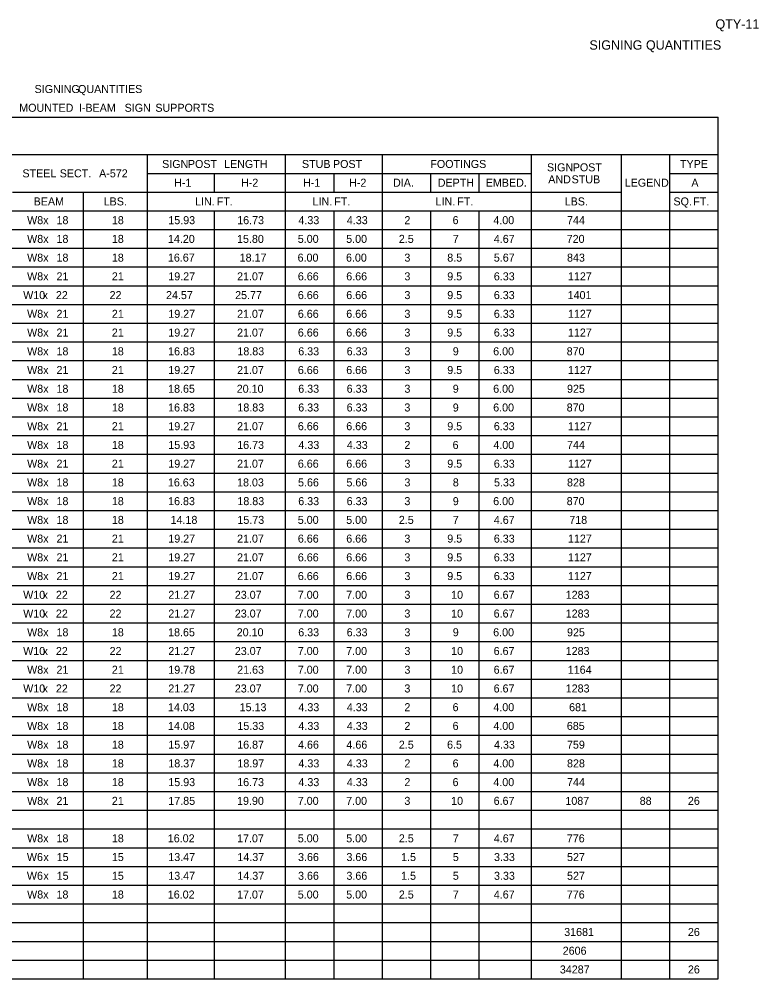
# Model space of a CAD drawing. Extents: x 1226631 to 1228126, y 151309 to 152305.
# Drawn here: x 1227650 to 1228112, y 151706 to 152305 of the extents above; entities that cross this region are included whole.
import ezdxf

# ---------------------------------------------------------------- set-up
doc = ezdxf.new("R2010")
doc.units = 0
doc.layers.add('R_Border', color=7, linetype='Continuous')
doc.layers.add('R_Dimension', color=7, linetype='Continuous')

msp = doc.modelspace()

# ---------------------------------------------------------------- linework, layer by layer
at = {"layer": 'R_Dimension'}
for p, q in [((1227303.08, 152244.32), (1228086.49, 152244.32)), ((1228086.49, 151706.12), (1228086.49, 152244.32)), ((1227540.49, 152220.92), (1228086.49, 152220.92)), ((1227730.13, 151706.12), (1227730.13, 152220.92)), ((1227816.42, 151706.12), (1227816.42, 152220.92)), ((1227876.87, 151706.12), (1227876.87, 152220.92)), ((1227969.98, 151706.12), (1227969.98, 152220.92)), ((1228026.04, 151706.12), (1228026.04, 152220.92)), ((1228056.27, 151706.12), (1228056.27, 152220.92)), ((1227730.13, 152209.22), (1227969.98, 152209.22)), ((1227772.05, 152197.52), (1227772.05, 152209.22)), ((1227846.64, 152197.52), (1227846.64, 152209.22)), ((1227907.09, 152197.52), (1227907.09, 152209.22)), ((1227937.32, 152197.52), (1227937.32, 152209.22)), ((1228056.27, 152209.22), (1228086.49, 152209.22)), ((1227645.79, 152197.52), (1228026.04, 152197.52)), ((1227690.15, 151706.12), (1227690.15, 152197.52)), ((1227969.98, 152197.52), (1228026.04, 152197.52)), ((1228056.27, 152197.52), (1228086.49, 152197.52)), ((1227303.08, 152185.82), (1228086.49, 152185.82)), ((1227772.05, 151706.12), (1227772.05, 152185.82)), ((1227846.64, 151706.12), (1227846.64, 152185.82)), ((1227907.09, 151706.12), (1227907.09, 152185.82)), ((1227937.32, 151706.12), (1227937.32, 152185.82)), ((1228026.04, 152185.82), (1228086.49, 152185.82)), ((1227303.08, 152174.12), (1228086.49, 152174.12)), ((1227303.08, 152162.42), (1228086.49, 152162.42)), ((1227303.08, 152150.72), (1228086.49, 152150.72)), ((1227303.08, 152139.02), (1228086.49, 152139.02)), ((1227303.08, 152127.32), (1228086.49, 152127.32)), ((1227303.08, 152115.62), (1228086.49, 152115.62)), ((1227303.08, 152103.92), (1228086.49, 152103.92)), ((1227303.08, 152092.22), (1228086.49, 152092.22)), ((1227303.08, 152080.52), (1228086.49, 152080.52)), ((1227303.08, 152068.82), (1228086.49, 152068.82)), ((1227303.08, 152057.12), (1228086.49, 152057.12)), ((1227303.08, 152045.42), (1228086.49, 152045.42)), ((1227303.08, 152033.72), (1228086.49, 152033.72)), ((1227303.08, 152022.02), (1228086.49, 152022.02)), ((1227303.08, 152010.32), (1228086.49, 152010.32)), ((1227303.08, 151998.62), (1228086.49, 151998.62)), ((1227303.08, 151986.92), (1228086.49, 151986.92)), ((1227303.08, 151975.22), (1228086.49, 151975.22)), ((1227303.08, 151963.52), (1228086.49, 151963.52)), ((1227303.08, 151951.82), (1228086.49, 151951.82)), ((1227303.08, 151940.12), (1228086.49, 151940.12)), ((1227303.08, 151928.42), (1228086.49, 151928.42)), ((1227303.08, 151916.72), (1228086.49, 151916.72)), ((1227303.08, 151905.02), (1228086.49, 151905.02)), ((1227303.08, 151893.32), (1228086.49, 151893.32)), ((1227303.08, 151881.62), (1228086.49, 151881.62)), ((1227303.08, 151869.92), (1228086.49, 151869.92)), ((1227303.08, 151858.22), (1228086.49, 151858.22)), ((1227303.08, 151846.52), (1228086.49, 151846.52)), ((1227303.08, 151834.82), (1228086.49, 151834.82)), ((1227303.08, 151823.12), (1228086.49, 151823.12)), ((1227303.08, 151811.42), (1228086.49, 151811.42)), ((1227303.08, 151799.72), (1228086.49, 151799.72)), ((1227303.08, 151788.02), (1228086.49, 151788.02)), ((1227303.08, 151776.32), (1228086.49, 151776.32)), ((1227303.08, 151764.62), (1228086.49, 151764.62)), ((1227303.08, 151752.92), (1228086.49, 151752.92)), ((1227303.08, 151741.22), (1228086.49, 151741.22)), ((1227303.08, 151729.52), (1228086.49, 151729.52)), ((1227303.08, 151717.82), (1228086.49, 151717.82)), ((1227303.08, 151706.12), (1228086.49, 151706.12))]:
    msp.add_line(p, q, dxfattribs=at)

# ---------------------------------------------------------------- texts
at = {"layer": 'R_Border'}
for s, height, p in [('QTY-11', 5.861, (1228084.79, 152299.55)), ('SIGNING QUANTITIES', 5.862, (1228006.08, 152286.45))]:
    msp.add_text(s, height=height, dxfattribs=at).set_placement(p)
at = {"layer": 'R_Dimension'}
for s, p in [('SIGNING', (1227659.63, 152259.37)), (' QUANTITIES', (1227684.94, 152259.37)), (' MOUNTED', (1227648.21, 152247.67)), (' I-BEAM', (1227685.45, 152247.67)), (' SIGN', (1227714, 152247.67)), (' SUPPORTS', (1227733.21, 152247.67)), ('SIGN', (1227739.3, 152212.57)), (' POST', (1227753.51, 152212.57)), (' LENGTH', (1227776.11, 152212.57)), ('STUB', (1227826.58, 152212.57)), (' POST', (1227844.1, 152212.57)), ('FOOTINGS', (1227906.77, 152212.57)), ('TYPE', (1228062.64, 152212.57)), ('STEEL', (1227652.05, 152206.72)), (' SECT.', (1227673.47, 152206.72)), (' A-572', (1227698.08, 152206.72)), ('SIGN', (1227979.6, 152210.47)), (' POST', (1227993.82, 152210.47)), ('H-1', (1227746.8, 152200.87)), ('H-2', (1227788.53, 152200.87)), ('H-1', (1227827.24, 152200.87)), ('H-2', (1227856.04, 152200.87)), ('DIA.', (1227883.45, 152200.87)), ('DEPTH', (1227911.38, 152200.87)), ('EMBED.', (1227941.36, 152200.87)), ('AND', (1227980.39, 152202.97)), (' STUB', (1227993.11, 152202.97)), ('LEGEND', (1228028.14, 152200.87)), ('A', (1228069.74, 152200.87)), ('BEAM', (1227659.07, 152189.17)), ('LBS.', (1227702.78, 152189.17)), ('LIN.', (1227759.87, 152189.17)), (' FT.', (1227771.52, 152189.17)), ('LIN.', (1227833.24, 152189.17)), (' FT.', (1227844.89, 152189.17)), ('LIN.', (1227910.02, 152189.17)), (' FT.', (1227921.67, 152189.17)), ('LBS.', (1227990.65, 152189.17)), ('SQ.', (1228058.56, 152189.17)), (' FT.', (1228069.04, 152189.17)), ('W8', (1227654.98, 152177.47)), (' x', (1227663.17, 152177.47)), (' 18', (1227671.48, 152177.47)), ('18', (1227707.9, 152177.47)), ('15.93', (1227743.14, 152177.47)), ('16.73', (1227786.16, 152177.47)), ('4.33', (1227824.4, 152177.47)), ('4.33', (1227854.63, 152177.47)), ('2', (1227890.56, 152177.47)), ('6', (1227920.65, 152177.47)), ('4.00', (1227946.11, 152177.47)), ('744', (1227992.1, 152177.47)), ('W8', (1227654.98, 152165.77)), (' x', (1227663.17, 152165.77)), (' 18', (1227671.48, 152165.77)), ('18', (1227707.9, 152165.77)), ('14.20', (1227742.92, 152165.77)), ('15.80', (1227786.07, 152165.77)), ('5.00', (1227823.99, 152165.77)), ('5.00', (1227854.21, 152165.77)), ('2.5', (1227887.1, 152165.77)), ('7', (1227920.79, 152165.77)), ('4.67', (1227946.4, 152165.77)), ('720', (1227991.89, 152165.77)), ('W8', (1227654.98, 152154.07)), (' x', (1227663.17, 152154.07)), (' 18', (1227671.48, 152154.07)), ('18', (1227707.9, 152154.07)), ('16.67', (1227742.9, 152154.07)), ('18.17', (1227787.7, 152154.07)), ('6.00', (1227823.87, 152154.07)), ('6.00', (1227854.1, 152154.07)), ('3', (1227890.56, 152154.07)), ('8.5', (1227917.32, 152154.07)), ('5.67', (1227946.4, 152154.07)), ('843', (1227992.1, 152154.07)), ('W8', (1227654.98, 152142.37)), (' x', (1227663.17, 152142.37)), (' 21', (1227671.48, 152142.37)), ('21', (1227707.9, 152142.37)), ('19.27', (1227743.14, 152142.37)), ('21.07', (1227786.09, 152142.37)), ('6.66', (1227824.03, 152142.37)), ('6.66', (1227854.25, 152142.37)), ('3', (1227890.56, 152142.37)), ('9.5', (1227917.32, 152142.37)), ('6.33', (1227946.4, 152142.37)), ('1127', (1227992.69, 152142.37)), ('W10', (1227652.52, 152130.67)), (' x', (1227662.8, 152130.67)), (' 22', (1227671.1, 152130.67)), ('22', (1227706.48, 152130.67)), ('24.57', (1227741.72, 152130.67)), ('25.77', (1227784.86, 152130.67)), ('6.66', (1227824.03, 152130.67)), ('6.66', (1227854.25, 152130.67)), ('3', (1227890.56, 152130.67)), ('9.5', (1227917.32, 152130.67)), ('6.33', (1227946.4, 152130.67)), ('1401', (1227992.5, 152130.67)), ('W8', (1227654.98, 152118.97)), (' x', (1227663.17, 152118.97)), (' 21', (1227671.48, 152118.97)), ('21', (1227707.9, 152118.97)), ('19.27', (1227743.14, 152118.97)), ('21.07', (1227786.09, 152118.97)), ('6.66', (1227824.03, 152118.97)), ('6.66', (1227854.25, 152118.97)), ('3', (1227890.56, 152118.97)), ('9.5', (1227917.32, 152118.97)), ('6.33', (1227946.4, 152118.97)), ('1127', (1227992.69, 152118.97)), ('W8', (1227654.98, 152107.27)), (' x', (1227663.17, 152107.27)), (' 21', (1227671.48, 152107.27)), ('21', (1227707.9, 152107.27)), ('19.27', (1227743.14, 152107.27)), ('21.07', (1227786.09, 152107.27)), ('6.66', (1227824.03, 152107.27)), ('6.66', (1227854.25, 152107.27)), ('3', (1227890.56, 152107.27)), ('9.5', (1227917.32, 152107.27)), ('6.33', (1227946.4, 152107.27)), ('1127', (1227992.69, 152107.27)), ('W8', (1227654.98, 152095.57)), (' x', (1227663.17, 152095.57)), (' 18', (1227671.48, 152095.57)), ('18', (1227707.9, 152095.57)), ('16.83', (1227743.02, 152095.57)), ('18.83', (1227786.28, 152095.57)), ('6.33', (1227824.28, 152095.57)), ('6.33', (1227854.51, 152095.57)), ('3', (1227890.56, 152095.57)), ('9', (1227920.77, 152095.57)), ('6.00', (1227945.99, 152095.57)), ('870', (1227991.89, 152095.57)), ('W8', (1227654.98, 152083.87)), (' x', (1227663.17, 152083.87)), (' 21', (1227671.48, 152083.87)), ('21', (1227707.9, 152083.87)), ('19.27', (1227743.14, 152083.87)), ('21.07', (1227786.09, 152083.87)), ('6.66', (1227824.03, 152083.87)), ('6.66', (1227854.25, 152083.87)), ('3', (1227890.56, 152083.87)), ('9.5', (1227917.32, 152083.87)), ('6.33', (1227946.4, 152083.87)), ('1127', (1227992.69, 152083.87)), ('W8', (1227654.98, 152072.17)), (' x', (1227663.17, 152072.17)), (' 18', (1227671.48, 152072.17)), ('18', (1227707.9, 152072.17)), ('18.65', (1227743.02, 152072.17)), ('20.10', (1227785.87, 152072.17)), ('6.33', (1227824.28, 152072.17)), ('6.33', (1227854.51, 152072.17)), ('3', (1227890.56, 152072.17)), ('9', (1227920.77, 152072.17)), ('6.00', (1227945.99, 152072.17)), ('925', (1227992.1, 152072.17)), ('W8', (1227654.98, 152060.47)), (' x', (1227663.17, 152060.47)), (' 18', (1227671.48, 152060.47)), ('18', (1227707.9, 152060.47)), ('16.83', (1227743.02, 152060.47)), ('18.83', (1227786.28, 152060.47)), ('6.33', (1227824.28, 152060.47)), ('6.33', (1227854.51, 152060.47)), ('3', (1227890.56, 152060.47)), ('9', (1227920.77, 152060.47)), ('6.00', (1227945.99, 152060.47)), ('870', (1227991.89, 152060.47)), ('W8', (1227654.98, 152048.77)), (' x', (1227663.17, 152048.77)), (' 21', (1227671.48, 152048.77)), ('21', (1227707.9, 152048.77)), ('19.27', (1227743.14, 152048.77)), ('21.07', (1227786.09, 152048.77)), ('6.66', (1227824.03, 152048.77)), ('6.66', (1227854.25, 152048.77)), ('3', (1227890.56, 152048.77)), ('9.5', (1227917.32, 152048.77)), ('6.33', (1227946.4, 152048.77)), ('1127', (1227992.69, 152048.77)), ('W8', (1227654.98, 152037.07)), (' x', (1227663.17, 152037.07)), (' 18', (1227671.48, 152037.07)), ('18', (1227707.9, 152037.07)), ('15.93', (1227743.14, 152037.07)), ('16.73', (1227786.16, 152037.07)), ('4.33', (1227824.4, 152037.07)), ('4.33', (1227854.63, 152037.07)), ('2', (1227890.56, 152037.07)), ('6', (1227920.65, 152037.07)), ('4.00', (1227946.11, 152037.07)), ('744', (1227992.1, 152037.07)), ('W8', (1227654.98, 152025.37)), (' x', (1227663.17, 152025.37)), (' 21', (1227671.48, 152025.37)), ('21', (1227707.9, 152025.37)), ('19.27', (1227743.14, 152025.37)), ('21.07', (1227786.09, 152025.37)), ('6.66', (1227824.03, 152025.37)), ('6.66', (1227854.25, 152025.37)), ('3', (1227890.56, 152025.37)), ('9.5', (1227917.32, 152025.37)), ('6.33', (1227946.4, 152025.37)), ('1127', (1227992.69, 152025.37)), ('W8', (1227654.98, 152013.67)), (' x', (1227663.17, 152013.67)), (' 18', (1227671.48, 152013.67)), ('18', (1227707.9, 152013.67)), ('16.63', (1227742.9, 152013.67)), ('18.03', (1227786.09, 152013.67)), ('5.66', (1227824.15, 152013.67)), ('5.66', (1227854.37, 152013.67)), ('3', (1227890.56, 152013.67)), ('8', (1227920.79, 152013.67)), ('5.33', (1227946.52, 152013.67)), ('828', (1227992.1, 152013.67)), ('W8', (1227654.98, 152001.97)), (' x', (1227663.17, 152001.97)), (' 18', (1227671.48, 152001.97)), ('18', (1227707.9, 152001.97)), ('16.83', (1227743.02, 152001.97)), ('18.83', (1227786.28, 152001.97)), ('6.33', (1227824.28, 152001.97)), ('6.33', (1227854.51, 152001.97)), ('3', (1227890.56, 152001.97)), ('9', (1227920.77, 152001.97)), ('6.00', (1227945.99, 152001.97)), ('870', (1227991.89, 152001.97)), ('W8', (1227654.98, 151990.27)), (' 18', (1227671.48, 151990.27)), ('18', (1227707.9, 151990.27)), ('14.18', (1227744.56, 151990.27)), ('15.73', (1227786.28, 151990.27)), ('5.00', (1227823.99, 151990.27)), ('5.00', (1227854.21, 151990.27)), ('2.5', (1227887.1, 151990.27)), ('7', (1227920.79, 151990.27)), ('4.67', (1227946.4, 151990.27)), ('718', (1227993.52, 151990.27)), (' x', (1227663.17, 151990.27)), ('W8', (1227654.98, 151978.57)), (' 21', (1227671.48, 151978.57)), ('21', (1227707.9, 151978.57)), ('19.27', (1227743.14, 151978.57)), ('21.07', (1227786.09, 151978.57)), ('6.66', (1227824.03, 151978.57)), ('6.66', (1227854.25, 151978.57)), ('3', (1227890.56, 151978.57)), ('9.5', (1227917.32, 151978.57)), ('6.33', (1227946.4, 151978.57)), ('1127', (1227992.69, 151978.57)), (' x', (1227663.17, 151978.57)), ('W8', (1227654.98, 151966.87)), (' 21', (1227671.48, 151966.87)), ('21', (1227707.9, 151966.87)), ('19.27', (1227743.14, 151966.87)), ('21.07', (1227786.09, 151966.87)), ('6.66', (1227824.03, 151966.87)), ('6.66', (1227854.25, 151966.87)), ('3', (1227890.56, 151966.87)), ('9.5', (1227917.32, 151966.87)), ('6.33', (1227946.4, 151966.87)), ('1127', (1227992.69, 151966.87)), (' x', (1227663.17, 151966.87)), ('W8', (1227654.98, 151955.17)), (' 21', (1227671.48, 151955.17)), ('21', (1227707.9, 151955.17)), ('19.27', (1227743.14, 151955.17)), ('21.07', (1227786.09, 151955.17)), ('6.66', (1227824.03, 151955.17)), ('6.66', (1227854.25, 151955.17)), ('3', (1227890.56, 151955.17)), ('9.5', (1227917.32, 151955.17)), ('6.33', (1227946.4, 151955.17)), ('1127', (1227992.69, 151955.17)), (' x', (1227663.17, 151955.17)), ('W10', (1227652.52, 151943.47)), (' x', (1227662.8, 151943.47)), (' 22', (1227671.1, 151943.47)), ('22', (1227706.48, 151943.47)), ('21.27', (1227743.14, 151943.47)), ('23.07', (1227784.67, 151943.47)), ('7.00', (1227823.99, 151943.47)), ('7.00', (1227854.21, 151943.47)), ('3', (1227890.56, 151943.47)), ('10', (1227919.74, 151943.47)), ('6.67', (1227946.29, 151943.47)), ('1283', (1227991.28, 151943.47)), ('W10', (1227652.52, 151931.77)), (' x', (1227662.8, 151931.77)), (' 22', (1227671.1, 151931.77)), ('22', (1227706.48, 151931.77)), ('21.27', (1227743.14, 151931.77)), ('23.07', (1227784.67, 151931.77)), ('7.00', (1227823.99, 151931.77)), ('7.00', (1227854.21, 151931.77)), ('3', (1227890.56, 151931.77)), ('10', (1227919.74, 151931.77)), ('6.67', (1227946.29, 151931.77)), ('1283', (1227991.28, 151931.77)), ('W8', (1227654.98, 151920.07)), (' x', (1227663.17, 151920.07)), (' 18', (1227671.48, 151920.07)), ('18', (1227707.9, 151920.07)), ('18.65', (1227743.02, 151920.07)), ('20.10', (1227785.87, 151920.07)), ('6.33', (1227824.28, 151920.07)), ('6.33', (1227854.51, 151920.07)), ('3', (1227890.56, 151920.07)), ('9', (1227920.77, 151920.07)), ('6.00', (1227945.99, 151920.07)), ('925', (1227992.1, 151920.07)), ('W10', (1227652.52, 151908.37)), (' x', (1227662.8, 151908.37)), (' 22', (1227671.1, 151908.37)), ('22', (1227706.48, 151908.37)), ('21.27', (1227743.14, 151908.37)), ('23.07', (1227784.67, 151908.37)), ('7.00', (1227823.99, 151908.37)), ('7.00', (1227854.21, 151908.37)), ('3', (1227890.56, 151908.37)), ('10', (1227919.74, 151908.37)), ('6.67', (1227946.29, 151908.37)), ('1283', (1227991.28, 151908.37)), ('W8', (1227654.98, 151896.67)), (' x', (1227663.17, 151896.67)), (' 21', (1227671.48, 151896.67)), ('21', (1227707.9, 151896.67)), ('19.78', (1227743.14, 151896.67)), ('21.63', (1227786.16, 151896.67)), ('7.00', (1227823.99, 151896.67)), ('7.00', (1227854.21, 151896.67)), ('3', (1227890.56, 151896.67)), ('10', (1227919.74, 151896.67)), ('6.67', (1227946.29, 151896.67)), ('1164', (1227992.58, 151896.67)), ('W10', (1227652.52, 151884.97)), (' x', (1227662.8, 151884.97)), (' 22', (1227671.1, 151884.97)), ('22', (1227706.48, 151884.97)), ('21.27', (1227743.14, 151884.97)), ('23.07', (1227784.67, 151884.97)), ('7.00', (1227823.99, 151884.97)), ('7.00', (1227854.21, 151884.97)), ('3', (1227890.56, 151884.97)), ('10', (1227919.74, 151884.97)), ('6.67', (1227946.29, 151884.97)), ('1283', (1227991.28, 151884.97)), ('W8', (1227654.98, 151873.27)), (' x', (1227663.17, 151873.27)), (' 18', (1227671.48, 151873.27)), ('18', (1227707.9, 151873.27)), ('14.03', (1227742.94, 151873.27)), ('15.13', (1227787.7, 151873.27)), ('4.33', (1227824.4, 151873.27)), ('4.33', (1227854.63, 151873.27)), ('2', (1227890.56, 151873.27)), ('6', (1227920.65, 151873.27)), ('4.00', (1227946.11, 151873.27)), ('681', (1227993.4, 151873.27)), ('W8', (1227654.98, 151861.57)), (' x', (1227663.17, 151861.57)), (' 18', (1227671.48, 151861.57)), ('18', (1227707.9, 151861.57)), ('14.08', (1227742.94, 151861.57)), ('15.33', (1227786.28, 151861.57)), ('4.33', (1227824.4, 151861.57)), ('4.33', (1227854.63, 151861.57)), ('2', (1227890.56, 151861.57)), ('6', (1227920.65, 151861.57)), ('4.00', (1227946.11, 151861.57)), ('685', (1227991.99, 151861.57)), ('W8', (1227654.98, 151849.87)), (' x', (1227663.17, 151849.87)), (' 18', (1227671.48, 151849.87)), ('18', (1227707.9, 151849.87)), ('15.97', (1227743.14, 151849.87)), ('16.87', (1227786.16, 151849.87)), ('4.66', (1227824.15, 151849.87)), ('4.66', (1227854.37, 151849.87)), ('2.5', (1227887.1, 151849.87)), ('6.5', (1227917.2, 151849.87)), ('4.33', (1227946.52, 151849.87)), ('759', (1227992.08, 151849.87)), ('W8', (1227654.98, 151838.17)), (' x', (1227663.17, 151838.17)), (' 18', (1227671.48, 151838.17)), ('18', (1227707.9, 151838.17)), ('18.37', (1227743.14, 151838.17)), ('18.97', (1227786.28, 151838.17)), ('4.33', (1227824.4, 151838.17)), ('4.33', (1227854.63, 151838.17)), ('2', (1227890.56, 151838.17)), ('6', (1227920.65, 151838.17)), ('4.00', (1227946.11, 151838.17)), ('828', (1227992.1, 151838.17)), ('W8', (1227654.98, 151826.47)), (' x', (1227663.17, 151826.47)), (' 18', (1227671.48, 151826.47)), ('18', (1227707.9, 151826.47)), ('15.93', (1227743.14, 151826.47)), ('16.73', (1227786.16, 151826.47)), ('4.33', (1227824.4, 151826.47)), ('4.33', (1227854.63, 151826.47)), ('2', (1227890.56, 151826.47)), ('6', (1227920.65, 151826.47)), ('4.00', (1227946.11, 151826.47)), ('744', (1227992.1, 151826.47)), ('W8', (1227654.98, 151814.77)), (' x', (1227663.17, 151814.77)), (' 21', (1227671.48, 151814.77)), ('21', (1227707.9, 151814.77)), ('17.85', (1227743.14, 151814.77)), ('19.90', (1227786.07, 151814.77)), ('7.00', (1227823.99, 151814.77)), ('7.00', (1227854.21, 151814.77)), ('3', (1227890.56, 151814.77)), ('10', (1227919.74, 151814.77)), ('6.67', (1227946.29, 151814.77)), ('1087', (1227991.08, 151814.77)), ('88', (1228037.49, 151814.77)), ('26', (1228067.58, 151814.77)), ('W8', (1227654.98, 151791.37)), (' x', (1227663.17, 151791.37)), (' 18', (1227671.48, 151791.37)), ('18', (1227707.9, 151791.37)), ('16.02', (1227742.82, 151791.37)), ('17.07', (1227786.09, 151791.37)), ('5.00', (1227823.99, 151791.37)), ('5.00', (1227854.21, 151791.37)), ('2.5', (1227887.1, 151791.37)), ('7', (1227920.79, 151791.37)), ('4.67', (1227946.4, 151791.37)), ('776', (1227991.97, 151791.37)), ('W6', (1227654.84, 151779.67)), (' x', (1227663.31, 151779.67)), (' 15', (1227671.61, 151779.67)), ('15', (1227707.9, 151779.67)), ('13.47', (1227743.14, 151779.67)), ('14.37', (1227786.28, 151779.67)), ('3.66', (1227824.15, 151779.67)), ('3.66', (1227854.37, 151779.67)), ('1.5', (1227888.51, 151779.67)), ('5', (1227920.79, 151779.67)), ('3.33', (1227946.52, 151779.67)), ('527', (1227992.1, 151779.67)), ('W6', (1227654.84, 151767.97)), (' x', (1227663.31, 151767.97)), (' 15', (1227671.61, 151767.97)), ('15', (1227707.9, 151767.97)), ('13.47', (1227743.14, 151767.97)), ('14.37', (1227786.28, 151767.97)), ('3.66', (1227824.15, 151767.97)), ('3.66', (1227854.37, 151767.97)), ('1.5', (1227888.51, 151767.97)), ('5', (1227920.79, 151767.97)), ('3.33', (1227946.52, 151767.97)), ('527', (1227992.1, 151767.97)), ('W8', (1227654.98, 151756.27)), (' 18', (1227671.48, 151756.27)), ('18', (1227707.9, 151756.27)), ('16.02', (1227742.82, 151756.27)), ('17.07', (1227786.09, 151756.27)), ('5.00', (1227823.99, 151756.27)), ('5.00', (1227854.21, 151756.27)), ('2.5', (1227887.1, 151756.27)), ('4.67', (1227946.4, 151756.27)), ('776', (1227991.97, 151756.27)), (' x', (1227663.17, 151756.27)), ('7', (1227920.79, 151756.27)), ('31681', (1227990.33, 151732.87)), ('26', (1228067.58, 151732.87)), ('2606', (1227989.41, 151721.17)), ('34287', (1227987.62, 151709.47)), ('26', (1228067.58, 151709.47))]:
    msp.add_text(s, height=5, dxfattribs=at).set_placement(p)

doc.saveas('drawing.dxf')
